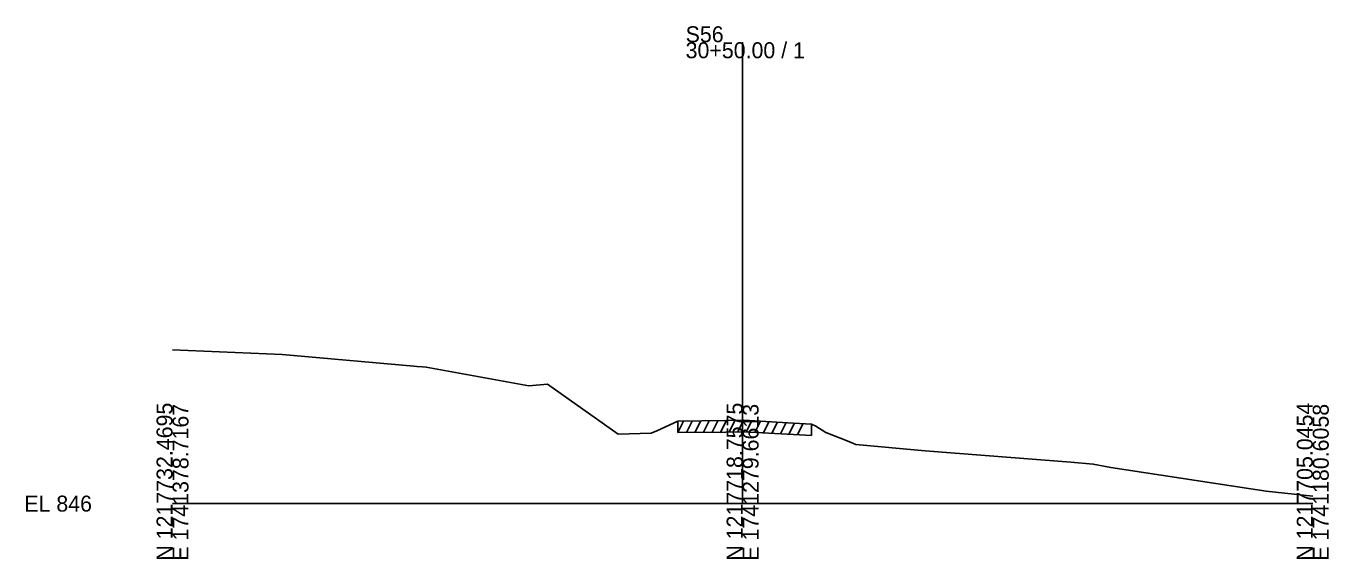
# Model space of a CAD drawing. Extents: x -26 to 1203, y -10 to 19541.
# Drawn here: x -25.7 to 202.8, y 5490.3 to 5583.7 of the extents above; entities that cross this region are included whole.
import ezdxf

# ---------------------------------------------------------------- set-up
doc = ezdxf.new("R2010")
doc.units = 0
for name, color, linetype in [('RD_GPK_XS_Cell', 7, 'Continuous'), ('RD_XS_ExGround', 7, 'Continuous'), ('RD_XS_ExPaveRet', 7, 'Continuous'), ('RD_XS_TX_Elev_EX', 7, 'Continuous')]:
    doc.layers.add(name, color=color, linetype=linetype)

msp = doc.modelspace()

# ---------------------------------------------------------------- linework, layer by layer
at = {"layer": 'RD_GPK_XS_Cell'}
for p, q in [((100, 5500), (100, 5580.86)), ((0, 5500), (100, 5500)), ((100, 5500), (200, 5500))]:
    msp.add_line(p, q, dxfattribs=at)
at = {"layer": 'RD_XS_ExGround'}
msp.add_lwpolyline([(0, 5526.95), (19.25, 5526.12), (21.23, 5525.95), (42.31, 5524.09), (42.83, 5524.05), (43.83, 5523.97), (44.5, 5523.9), (62.47, 5520.66), (65.8, 5520.96), (78.15, 5512.2), (83.93, 5512.32), (84.92, 5512.74), (88.63, 5514.44), (97.03, 5514.54), (100.2, 5514.6), (108.91, 5514.13), (112.1, 5513.95), (112.83, 5513.6), (114.61, 5512.49), (118.35, 5511.02), (119.87, 5510.35), (131.99, 5509.27), (157.57, 5507.25), (161.49, 5506.94), (164.6, 5506.36), (191.85, 5502.18), (200, 5501.29)], dxfattribs=at)
at = {"layer": 'RD_XS_ExPaveRet'}
for p, q in [((93.13, 5512.5), (94.14, 5514.51)), ((94.63, 5512.51), (95.64, 5514.53)), ((96.13, 5512.53), (97.14, 5514.54)), ((97.63, 5512.55), (98.64, 5514.57)), ((99.13, 5512.58), (100.14, 5514.6)), ((100.63, 5512.58), (101.61, 5514.52)), ((88.63, 5512.44), (89.64, 5514.46)), ((88.63, 5512.44), (88.63, 5514.44)), ((88.63, 5512.44), (97.03, 5512.54)), ((90.13, 5512.46), (91.14, 5514.47)), ((91.63, 5512.48), (92.64, 5514.49)), ((97.03, 5512.54), (100.2, 5512.6)), ((100.2, 5512.6), (108.91, 5512.13)), ((102.13, 5512.49), (103.11, 5514.44)), ((103.63, 5512.41), (104.61, 5514.36)), ((105.13, 5512.33), (106.11, 5514.28)), ((106.63, 5512.25), (107.61, 5514.2)), ((108.13, 5512.17), (109.11, 5514.12)), ((109.63, 5512.09), (110.61, 5514.03)), ((112.1, 5513.95), (112.1, 5511.95)), ((108.91, 5512.13), (112.1, 5511.95))]:
    msp.add_line(p, q, dxfattribs=at)

# ---------------------------------------------------------------- texts
at = {"layer": 'RD_GPK_XS_Cell'}
for s, p in [('S56', (90, 5580.86)), ('30+50.00 / 1', (90, 5578.06)), ('EL 846', (-26, 5498.6))]:
    msp.add_text(s, height=2.8, dxfattribs=at).set_placement(p)
for s, p in [('N 1217732.4695', (0, 5490)), ('E 1741378.7167', (2.8, 5490)), ('N 1217718.7575', (100, 5490)), ('E 1741279.6613', (102.8, 5490)), ('N 1217705.0454', (200, 5490)), ('E 1741180.6058', (202.8, 5490))]:
    msp.add_text(s, height=2.8, rotation=90, dxfattribs=at).set_placement(p)
at = {"layer": 'RD_XS_TX_Elev_EX'}
msp.add_text('853.30', height=0.1, rotation=90, dxfattribs=at).set_placement((100.1, 5514.6))

doc.saveas('drawing.dxf')
